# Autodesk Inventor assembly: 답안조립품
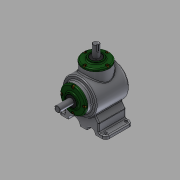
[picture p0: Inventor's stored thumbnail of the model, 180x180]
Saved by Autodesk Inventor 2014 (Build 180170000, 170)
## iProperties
Created: 2018-08
Part Number: 답안조립품
Document SubType Name: Weldment
Designer: user
Weld Material: Welded Aluminum-6061
Author: user
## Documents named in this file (14)
- C:\Users\user\Desktop\480808V1002\답안조립품.iam
- C:\Users\user\Desktop\480808V1002\메인 베벨기어.ipt
- C:\Users\user\Desktop\480808V1002\메인 축.ipt
- 메인 축.ipt
- C:\Users\user\Desktop\480808V1002\베어링 6203.ipt
- C:\Users\user\Desktop\480808V1002\본체.ipt
- C:\Users\user\Desktop\480808V1002\볼트 M4.ipt
- C:\Users\user\Desktop\480808V1002\서브 베벨기어.ipt
- C:\Users\user\Desktop\480808V1002\서브 축.ipt
- 서브 축.ipt
- C:\Users\user\Desktop\480808V1002\오일실 17 32 8.ipt
- C:\Users\user\Desktop\480808V1002\커버.ipt
- C:\Users\user\Desktop\480808V1002\키 4x4.ipt
- C:\Users\user\Desktop\480808V1002\키 5x5.ipt
